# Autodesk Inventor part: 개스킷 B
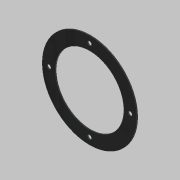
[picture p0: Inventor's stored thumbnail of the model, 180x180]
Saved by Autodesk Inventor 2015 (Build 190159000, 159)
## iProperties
Created: 2019-02
Part Number: 개스킷 B
Material: 고무
Document SubType Name: Modeling
Designer: mduedu
Density: 1 g/cm^3
Appearance: 고무 - 검은색 - 버전 1.1
Author: mduedu
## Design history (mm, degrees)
sketch "스케치1"
  geometry: C1 r 52.5 at (0, 0); C2 r 38 at (0, 0); 1 further point
  constraints: 2 centre point, 2 coincident
  dimensions: "d0" = 105 diameter of C1; "d1" = 76 diameter of C2
extrude "돌출1" new body sketch "스케치1" distance "d2" = 1; taper "d3" = 0 deg
sketch "스케치2" dims "d4" = 90
  geometry: 3 further points
  constraints: 2 vertical alignment, 1 coincident, 2 other
hole "구멍1" sketch "스케치2" at (0, 45) diameter "d5" = 4.5; stored, may be unused: countersink angle "d9" = 90 deg, drill point angle "d11" = 118 deg; dims "d6" = 6, "d7" = 4, "d8" = 2, "d10" = 8
node "솔리드1"
pattern_circular "원형 패턴1" dims angle "d13" = 360 deg
